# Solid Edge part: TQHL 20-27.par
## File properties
Author: LABUSIG
Template: iso metric part.par
Last saved by: LABUSIG
Revision: 2
Application: Solid Edge
Accuracy: 0.990
Username: LABUSIG
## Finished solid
Body 1: solid body, 129 faces, 397 edges, 267 vertices.
  Faces by surface: plane 72, torus 28, cylinder 21, spline 8
  Edges by curve: line 211, circle 104, curve on surface 47, spline 35
Bounding box of the edges (mm; curved faces can reach further): 20.500 x 29.030 x 120.000, from (0, 0, -120) to (20.5, 29.03, 0).
Cylindrical faces by radius (mm): R1 x2, R1.5 x2, R2 x4, R2.1 x4, R2.5 x2, R3 x1, R3.12 x2, R6 x1, R15 x3
Toroidal faces (ring radius, tube radius in mm): R2.1885 r0.8 x8, R3.9619 r0.8 x4, R5.4385 r0.8 x8, R26.0615 r0.8 x8
Planar faces by outward normal: +x 7, +y 2, +z 2, -x 5, -y 2, -z 2, oblique 52
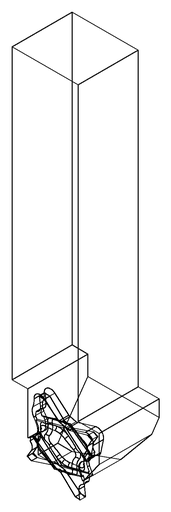
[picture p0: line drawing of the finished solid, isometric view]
